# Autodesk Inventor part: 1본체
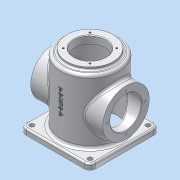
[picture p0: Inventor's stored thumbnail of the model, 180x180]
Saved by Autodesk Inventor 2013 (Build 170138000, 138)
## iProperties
Created: 2015-10
Part Number: 1본체
Material: 알루미늄 6061
Document SubType Name: Modeling
Designer: Administrator
Density: 2.71 g/cm^3
Mass: 988.868 g
Surface Area: 1039.98 cm^2
Volume: 364.896 cm^3
Author: Administrator
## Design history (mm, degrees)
sketch "스케치1"
  geometry: L1 (-60, 60)-(60, 60); L2 (60, 60)-(60, -60); L3 (60, -60)-(-60, -60); L4 (-60, -60)-(-60, 60); 3 further points
  constraints: 8 end point, 2 midpoint, 2 parallel, 2 perpendicular, 1 horizontal, 1 horizontal alignment, 1 vertical alignment
  dimensions: "d0" = 120 distance of L1.start L1.end
extrude "돌출1" new body sketch "스케치1" distance "d2" = 10; taper "d3" = 0 deg
sketch "스케치2"
  geometry: C1 r 50 at (0, 0); 1 further point
  constraints: 1 centre point, 1 coincident
  dimensions: "d4" = 100 diameter of C1
extrude "돌출2" join sketch "스케치2" distance "d6" = 110; taper "d7" = 0 deg
sketch "스케치3"
  geometry: C1 r 40 at (0, 60); 1 further point
  constraints: 1 centre point, 1 vertical alignment
  dimensions: "d8" = 80 diameter of C1; "d10" = 60 distance of C1.centre point (0, 0)
extrude "돌출3" join sketch "스케치3" stored distance "d11" = 124; taper "d12" = 0 deg
sketch "스케치4"
  geometry: C1 r 40 at (0, 0); 1 further point
  constraints: 1 centre point, 1 coincident
  dimensions: "d13" = 80 diameter of C1
extrude "돌출4" join sketch "스케치4" distance "d15" = 5; taper "d16" = 0 deg
sketch "스케치5"
  geometry: L1 (-48.178, 55.165)-(-48.178, 84.835); L2 (-48.178, 84.835)-(48.178, 84.835); L3 (48.178, 84.835)-(48.178, 55.165); L4 (48.178, 55.165)-(-48.178, 55.165); 4 further points
  constraints: 2 midpoint, 2 vertical alignment, 1 horizontal alignment, 2 other
  dimensions: "d17" = 70 distance of point (0, 70) point (0, 0)
feature "엠보싱1" sketch "스케치5" dims "d0" = 120, "d18" = 0.5, "d19" = 0
hole "구멍1" diameter "d22" = 54; stored, may be unused: countersink angle "d26" = 90 deg, drill point angle "d28" = 0 deg; dims "d20" = 10, "d21" = 10, "d23" = 6, "d24" = 54, "d25" = 13, "d27" = 124
sketch "스케치7"
  geometry: L1 (40, 125)-(-40, 125) reference; L2 (-60, 0)-(60, 0) reference; L3 (0, 125)-(0, 0); L4 (0, 125)-(27, 125); L5 (27, 112)-(45, 112); L6 (45, 112)-(45, 0); L7 (27, 125)-(27, 112); L8 (45, 0)-(0, 0)
  constraints: 12 end point, 2 parallel, 2 perpendicular, 2 point on line, 1 collinear, 1 midpoint
  dimensions: "d29" = 54 diameter of L7 L3; "d31" = 90 diameter of L6 L3; "d32" = 13 distance from line of L5.start L1
revolve "회전1" sketch "스케치7" stored, may be unused: angle "d33" = 90 deg
sketch "스케치8"
  geometry: A1 r 32.5 centre (0, 0) between (-22.981, 22.981) and (22.981, 22.981); 3 further points
  constraints: 4 point on circle, 2 horizontal alignment, 2 vertical alignment, 1 centre point, 1 coincident
  dimensions: "d34" = 65 diameter of A1; "d36" = 90 deg dimension on point (0, 0) A1.end A1.start
hole "구멍2" sketch "스케치8" at (-22.981, 22.981), (22.981, 22.981), (-22.981, -22.981), (22.981, -22.981) diameter "d38" = 3.242; stored, may be unused: countersink angle "d42" = 90 deg, drill point angle "d44" = 118 deg; dims "d39" = 8, "d40" = 54, "d41" = 13, "d43" = 10
sketch "스케치10"
  geometry: A1 r 32.5 centre (0, 0) between (32.5, 0) and (0, 32.5); 5 further points
  constraints: 4 point on circle, 3 vertical alignment, 2 horizontal alignment, 1 centre point, 2 other
  dimensions: "d45" = 60 distance of A1.centre point (0, -60); "d46" = 65 diameter of A1
hole "구멍3" sketch "스케치10" at (0, 32.5), (0, -32.5), (-32.5, 0), (32.5, 0) diameter "d47" = 3.242; stored, may be unused: countersink angle "d51" = 90 deg, drill point angle "d53" = 118 deg; dims "d48" = 8, "d49" = 54, "d50" = 13, "d52" = 10
sketch "스케치11"
  geometry: C1 r 4 at (-50, 50); C2 r 4 at (50, 50); C3 r 4 at (50, -50); C4 r 4 at (-50, -50); 1 further point
  constraints: 4 centre point, 3 equal radius, 2 horizontal alignment, 2 vertical alignment
  dimensions: "d54" = 8 diameter of C1; "d56" = 100 distance of C2.centre C1.centre; "d57" = 50 horizontal distance of point (0, 0) C1.centre; "d58" = 100 distance of C1.centre C4.centre; "d59" = 50 horizontal distance of point (0, 0) C1.centre
extrude "돌출5" cut sketch "스케치11" stored distance "d60" = 5; taper "d61" = 0 deg
fillet "모깎기1" dims "d62" = 10
chamfer "모따기1" distance "d63" = 1; stored, may be unused: second distance "d64" = 2, angle "d65" = 45 deg
chamfer "모따기2" distance "d66" = 1; stored, may be unused: second distance "d67" = 2, angle "d68" = 45 deg
chamfer "모따기3" distance "d69" = 3; stored, may be unused: second distance "d70" = 2, angle "d71" = 45 deg
fillet "모깎기3" dims "d73" = 5
fillet "모깎기4" dims "d74" = 3
fillet "모깎기5" dims "d75" = 3
fillet "모깎기7" dims "d77" = 3
fillet "모깎기9" dims "d79" = 5
fillet "모깎기10" dims "d80" = 5
fillet "모깎기11" dims "d81" = 3
node "솔리드1"
mirror "대칭1"
